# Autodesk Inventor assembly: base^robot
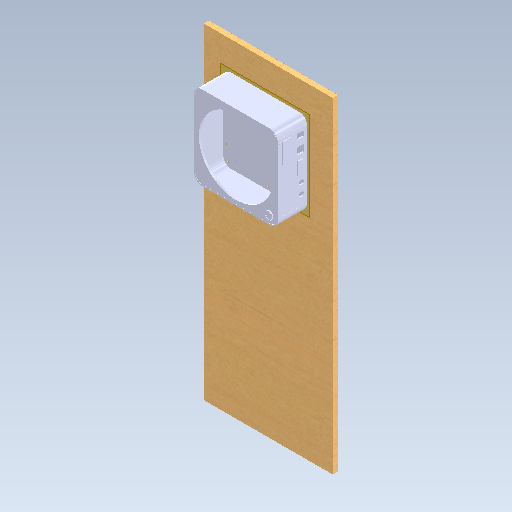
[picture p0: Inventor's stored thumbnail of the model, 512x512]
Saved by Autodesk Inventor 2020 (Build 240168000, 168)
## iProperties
Created: 2018-10
Part Number: base^robot
Document SubType Name: Assembly
Designer: bruno
Sending System: SolidWorks 2016
Last Author: Prof
Last Saved: 2018-10-31
Author: bruno
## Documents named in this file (14)
- C:\Users\bruno\Documents\Systèmes\Mallette Bras robotisé (273265)\Dossier ressources\Maquette Dobot SW2016\base^robot.iam
- C:\Users\bruno\Documents\Systèmes\Mallette Bras robotisé (273265)\Dossier ressources\Maquette Dobot SW2016\__10PIN___A.ipt
- C:\Users\bruno\Documents\Systèmes\Mallette Bras robotisé (273265)\Dossier ressources\Maquette Dobot SW2016\_________A.ipt
- C:\Users\bruno\Documents\Systèmes\Mallette Bras robotisé (273265)\Dossier ressources\Maquette Dobot SW2016\________230_A.ipt
- C:\Users\bruno\Documents\Systèmes\Mallette Bras robotisé (273265)\Dossier ressources\Maquette Dobot SW2016\___16_A.ipt
- C:\Users\bruno\Documents\Systèmes\Mallette Bras robotisé (273265)\Dossier ressources\Maquette Dobot SW2016\__15_A.ipt
- C:\Users\bruno\Documents\Systèmes\Mallette Bras robotisé (273265)\Dossier ressources\Maquette Dobot SW2016\____3_A_ASM.iam
- C:\Users\bruno\Documents\Systèmes\Mallette Bras robotisé (273265)\Dossier ressources\Maquette Dobot SW2016\___0_5MM_A.ipt
- C:\Users\bruno\Documents\Systèmes\Mallette Bras robotisé (273265)\Dossier ressources\Maquette Dobot SW2016\MSFS012_A.ipt
- C:\Users\bruno\Documents\Systèmes\Mallette Bras robotisé (273265)\Dossier ressources\Maquette Dobot SW2016\_______5_A.ipt
- C:\Users\bruno\Documents\Systèmes\Mallette Bras robotisé (273265)\Dossier ressources\Maquette Dobot SW2016\MSCS0403_A.ipt
- C:\Users\bruno\Documents\Systèmes\Mallette Bras robotisé (273265)\Dossier ressources\Maquette Dobot SW2016\__4_A.ipt
- C:\Users\bruno\Documents\Systèmes\Mallette Bras robotisé (273265)\Dossier ressources\Maquette Dobot SW2016\___________A.ipt
- C:\Users\bruno\Documents\Systèmes\Mallette Bras robotisé (273265)\Dossier ressources\Maquette Dobot SW2016\sol.ipt
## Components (18 placed, 13 different names)
1. __10PIN___A:1
2. _________A:1
3. ________230_A:1
4. ___16_A:1
5. __15_A:1
6. __15_A:2 — Affleurement:2
7. __15_A:3
8. __15_A:4
9. ____3_A_ASM:1 [sub-assembly]
10. ___0_5MM_A:1
11. MSFS012_A:1
12. MSFS012_A:2
13. _______5_A:1
14. MSCS0403_A:1
15. MSCS0403_A:2
16. __4_A:1 — Affleurement:1, Affleurement:3
17. ___________A:1
18. sol:1 — Affleurement:1, Affleurement:2, Affleurement:3
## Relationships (3: Flush 3)
- Affleurement:1 [Flush]: __4_A:1 ↔ sol:1
- Affleurement:2 [Flush]: __15_A:2 ↔ sol:1
- Affleurement:3 [Flush]: __4_A:1 ↔ sol:1
